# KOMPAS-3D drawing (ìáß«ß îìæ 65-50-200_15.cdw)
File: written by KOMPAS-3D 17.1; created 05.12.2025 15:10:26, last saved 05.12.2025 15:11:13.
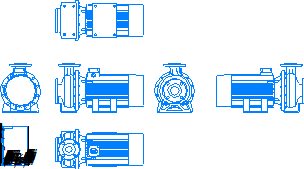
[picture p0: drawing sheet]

Sheet 1: A4, portrait

Title block, sheet 1: name: Насос МНС / 65-50-200_15; material: Сталь 10  ГОСТ 1050-88; mass: 194,11; sheets: 1; sheet format: A4

Views: Вид 1, Спереди, Проекционный вид 2, Проекционный вид 3, Проекционный вид 4, Проекционный вид 6
Referenced files in \\adlc.lan\data\АДЛ_ПКД\3D-модели\ADL production\Насосы ГРАНПАМП\Насосы ГРАНПАМП серии МНС\KOMPAS 3D\: Насос МНС 65-50-200_15.m3d
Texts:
  Andrey
  АДЛ
Dimensions and other numbers on the sheet: 1:1; 1; 65-50-200_15; 194,11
